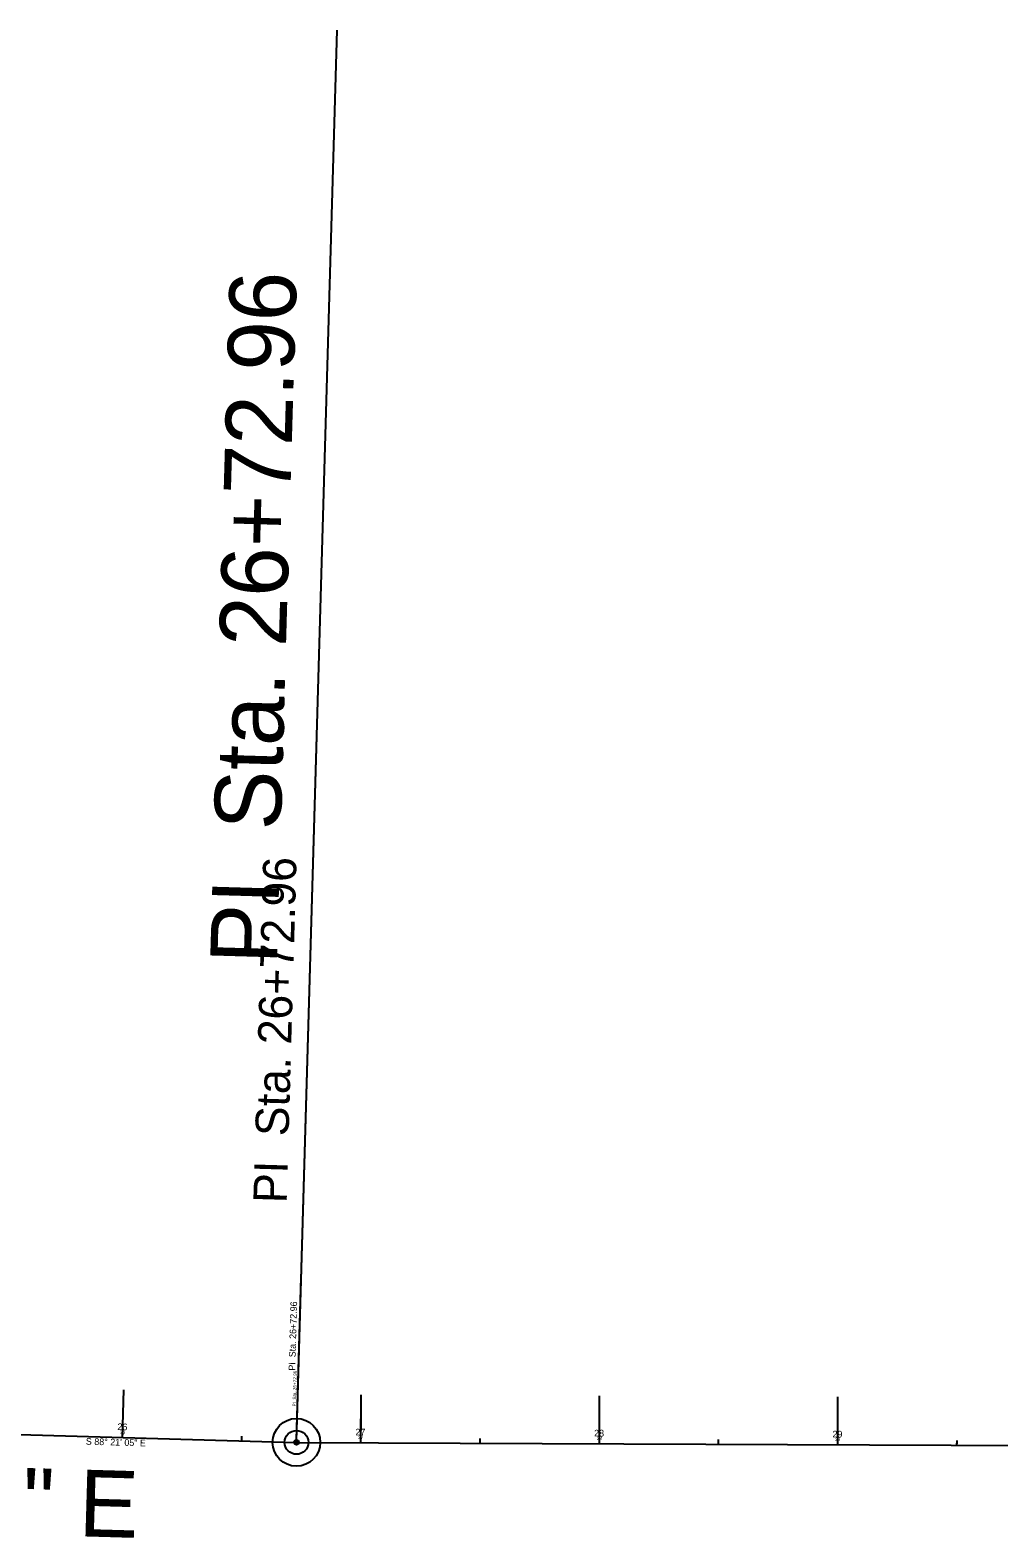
# Model space of a CAD drawing. Extents: x 1794716 to 1797874, y 325521 to 329174.
# Drawn here: x 1796818 to 1797225, y 327471 to 328103 of the extents above; entities that cross this region are included whole.
import ezdxf

# ---------------------------------------------------------------- set-up
doc = ezdxf.new("R2010")
doc.units = 0
for name, color, linetype in [('GE_P_CL_10', 7, 'Continuous'), ('GE_P_CL_100', 7, 'Continuous'), ('GE_P_CL_20', 7, 'Continuous'), ('GE_P_CL_200', 7, 'Continuous'), ('GE_P_CL_25', 7, 'Continuous'), ('GE_X_CL_30', 7, 'Continuous')]:
    doc.layers.add(name, color=color, linetype=linetype)

msp = doc.modelspace()

# ---------------------------------------------------------------- linework, layer by layer
at = {"layer": 'GE_P_CL_10'}
for p, q in [((1796930.01, 327511.25), (1796930.99, 327545.36)), ((1796607.37, 327520.04), (1796930, 327510.75)), ((1796857.07, 327512.85), (1796857.09, 327513.85)), ((1796907.04, 327511.41), (1796907.07, 327512.41)), ((1796930, 327510.75), (1797864.11, 327506.74)), ((1796957.04, 327510.64), (1796957.04, 327511.64)), ((1797007.03, 327510.42), (1797007.04, 327511.42)), ((1797057.03, 327510.21), (1797057.04, 327511.21)), ((1797107.03, 327509.99), (1797107.04, 327510.99)), ((1797157.03, 327509.78), (1797157.04, 327510.78)), ((1797207.03, 327509.56), (1797207.04, 327510.56))]:
    msp.add_line(p, q, dxfattribs=at)
msp.add_circle((1796930, 327510.75), 0.5, dxfattribs=at)
at = {"layer": 'GE_P_CL_100'}
for p, q in [((1796930.14, 327515.75), (1796938.52, 327806.88)), ((1796607.37, 327520.04), (1796930, 327510.75)), ((1796857.07, 327512.85), (1796857.35, 327522.85)), ((1796957.04, 327510.64), (1796957.08, 327520.64)), ((1797057.03, 327510.21), (1797057.08, 327520.21)), ((1797157.03, 327509.78), (1797157.08, 327519.78)), ((1796930, 327510.75), (1797864.11, 327506.74))]:
    msp.add_line(p, q, dxfattribs=at)
msp.add_circle((1796930, 327510.75), 5, dxfattribs=at)
at = {"layer": 'GE_P_CL_20'}
for p, q in [((1796607.37, 327520.04), (1796930, 327510.75)), ((1796857.07, 327512.85), (1796857.12, 327514.85)), ((1796907.04, 327511.41), (1796907.1, 327513.41)), ((1796957.04, 327510.64), (1796957.04, 327512.64)), ((1796930, 327510.75), (1797864.11, 327506.74)), ((1797007.03, 327510.42), (1797007.04, 327512.42)), ((1797057.03, 327510.21), (1797057.04, 327512.21)), ((1797107.03, 327509.99), (1797107.04, 327511.99)), ((1797157.03, 327509.78), (1797157.04, 327511.78)), ((1797207.03, 327509.56), (1797207.04, 327511.56))]:
    msp.add_line(p, q, dxfattribs=at)
at = {"layer": 'GE_P_CL_200'}
for p, q in [((1796930.28, 327520.75), (1796947.04, 328103)), ((1796857.07, 327512.85), (1796857.64, 327532.84)), ((1796957.04, 327510.64), (1796957.12, 327530.64)), ((1797057.03, 327510.21), (1797057.12, 327530.21)), ((1797157.03, 327509.78), (1797157.12, 327529.78)), ((1796607.37, 327520.04), (1796930, 327510.75)), ((1796930, 327510.75), (1797864.11, 327506.74))]:
    msp.add_line(p, q, dxfattribs=at)
msp.add_circle((1796930, 327510.75), 10, dxfattribs=at)
at = {"layer": 'GE_P_CL_25'}
msp.add_line((1796930.03, 327511.75), (1796931.99, 327579.97), dxfattribs=at)
msp.add_circle((1796930, 327510.75), 1, dxfattribs=at)
at = {"layer": 'GE_X_CL_30'}
for p, q in [((1796607.37, 327520.04), (1796930, 327510.75)), ((1796930, 327510.75), (1797864.11, 327506.74))]:
    msp.add_line(p, q, dxfattribs=at)

# ---------------------------------------------------------------- texts
at = {"layer": 'GE_P_CL_10'}
for s, rotation, p in [('PI  Sta. 26+72.96', 88.3515, (1796929.73, 327525.77)), ('26', 358.3515, (1796855.97, 327514.38)), ('27', 359.75374, (1796955.88, 327512.14)), ('28', 359.75374, (1797055.94, 327511.71)), ('29', 359.75374, (1797155.92, 327511.28))]:
    msp.add_text(s, height=1.4, rotation=rotation, dxfattribs=at).set_placement(p)
at = {"layer": 'GE_P_CL_100'}
msp.add_text('PI  Sta. 26+72.96', height=14, rotation=88.3515, dxfattribs=at).set_placement((1796925.88, 327610.91))
at = {"layer": 'GE_P_CL_20'}
for s, rotation, p in [('S 88%%d 21\' 05" E', 358.3515, (1796841.63, 327509.78)), ('26', 358.3515, (1796854.88, 327515.92)), ('27', 359.75374, (1796954.72, 327513.65)), ('28', 359.75374, (1797054.84, 327513.22)), ('29', 359.75374, (1797154.8, 327512.79))]:
    msp.add_text(s, height=2.8, rotation=rotation, dxfattribs=at).set_placement(p)
at = {"layer": 'GE_P_CL_200'}
for s, rotation, p in [('PI  Sta. 26+72.96', 88.3515, (1796921.76, 327711.07)), ('S 88%%d 21\' 05" E', 358.3515, (1796611.58, 327477.9))]:
    msp.add_text(s, height=28, rotation=rotation, dxfattribs=at).set_placement(p)
at = {"layer": 'GE_P_CL_25'}
msp.add_text('PI  Sta. 26+72.96', height=2.8, rotation=88.3515, dxfattribs=at).set_placement((1796929.46, 327540.78))

doc.saveas('drawing.dxf')
